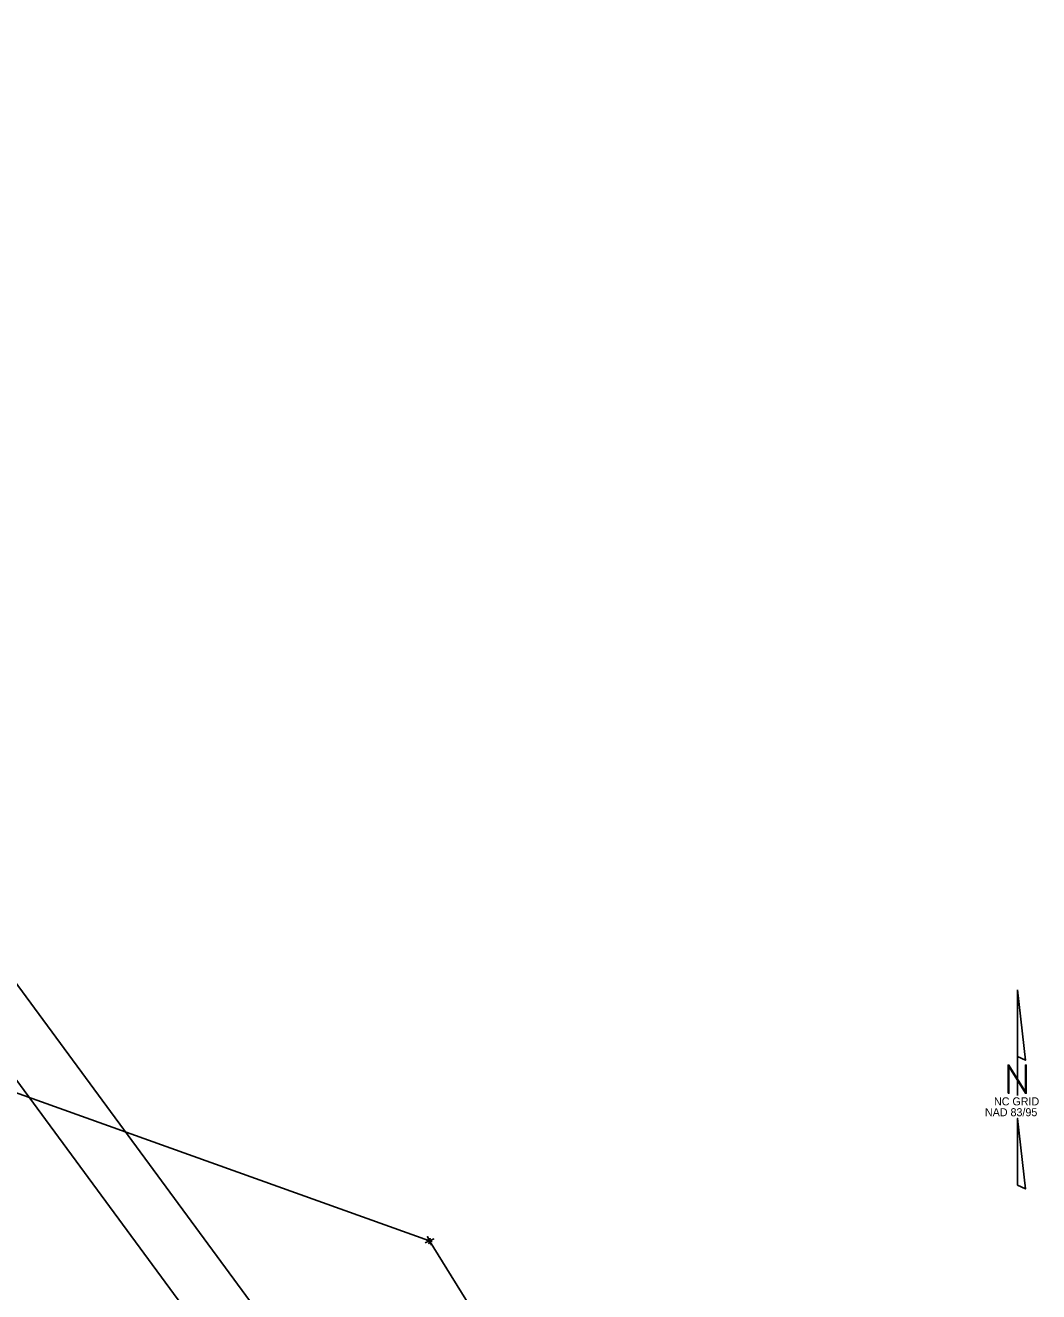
# Model space of a CAD drawing. Extents: x 2060057 to 2062431, y 911685 to 913703.
# Drawn here: x 2060679 to 2061210, y 913032 to 913696 of the extents above; entities that cross this region are included whole.
import ezdxf

# ---------------------------------------------------------------- set-up
doc = ezdxf.new("R2010")
doc.units = 0
for name, color, linetype in [('CTL North Arrow NAD 83 95 CELL', 7, 'Continuous'), ('Exist Property Corner CELL', 7, 'Continuous'), ('Exist Property Line', 7, 'Continuous'), ('Exist Utilities Power UG Cable', 7, 'Continuous')]:
    doc.layers.add(name, color=color, linetype=linetype)

# ---------------------------------------------------------------- blocks, each defined once
blk = doc.blocks.new('CTL NORTH ARROW NAD 83 95')
at = {"layer": 'CTL North Arrow NAD 83 95 CELL'}
for points in [[(-0.003, 1.746), (-0.003, 0.579), (0.135, 0.511)], [(-0.168, -0.065), (-0.154, -0.065), (-0.154, 0.401), (0.135, -0.065), (0.148, -0.065), (0.148, 0.428), (0.135, 0.428), (0.135, -0.038), (-0.154, 0.428), (-0.168, 0.428)], [(-0.003, -1.671), (0.135, -1.739), (-0.003, -0.505)]]:
    blk.add_lwpolyline(points, close=True, dxfattribs=at)
blk.add_lwpolyline([(-0.003, 0.579), (-0.003, -0.107)], dxfattribs=at)
for s, p in [('NC GRID', (-0.415, -0.277)), ('NAD 83/95', (-0.573, -0.467))]:
    blk.add_text(s, height=0.14, dxfattribs=at).set_placement(p)

msp = doc.modelspace()

# ---------------------------------------------------------------- linework, layer by layer
at = {"layer": 'Exist Property Corner CELL'}
msp.add_line((2060890.76, 913058.51), (2060890.76, 913058.51), dxfattribs=at)
msp.add_line((2060890.76, 913058.51), (2060890.76, 913058.51), dxfattribs=at)
for points in [[(2060888.5, 913057.45), (2060893.02, 913059.58), (2060890.76, 913058.51), (2060889.69, 913060.77), (2060891.83, 913056.25)], [(2060892.22, 913058.17), (2060889.3, 913058.86), (2060890.76, 913058.51), (2060890.41, 913057.05), (2060891.1, 913059.97)]]:
    msp.add_lwpolyline(points, dxfattribs=at)
at = {"layer": 'Exist Property Line'}
for p, q in [((2060203.77, 913304.6), (2060890.76, 913058.51)), ((2060890.76, 913058.51), (2060997.82, 912885.45))]:
    msp.add_line(p, q, dxfattribs=at)
at = {"layer": 'Exist Utilities Power UG Cable'}
for points in [[(2060304.19, 913696.4), (2061127.5, 912576.77)], [(2060280.08, 913678.67), (2061103.4, 912559.04)]]:
    msp.add_lwpolyline(points, dxfattribs=at)

# ---------------------------------------------------------------- block references
at = {"layer": 'CTL North Arrow NAD 83 95 CELL', "xscale": 30, "yscale": 30}
msp.add_blockref('CTL NORTH ARROW NAD 83 95', (2061199.24, 913137.93), dxfattribs=at)

doc.saveas('drawing.dxf')
